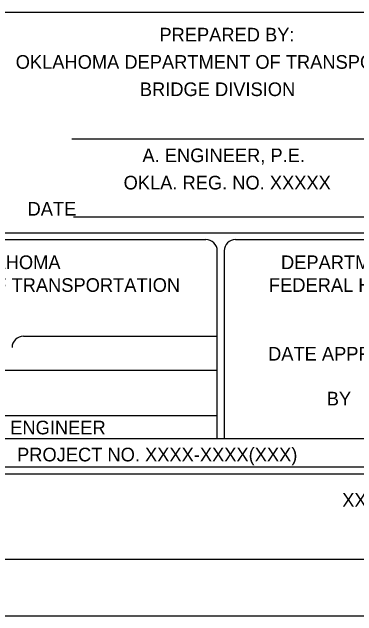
# Model space of a CAD drawing. Extents: x 1458004.1 to 1458040.9, y 194172.7 to 194198.1.
# Drawn here: x 1458033.92 to 1458036.94, y 194172.74 to 194178.05 of the extents above; entities that cross this region are included whole.
import ezdxf

# ---------------------------------------------------------------- set-up
doc = ezdxf.new("R2010")
doc.units = 0
for name, color, linetype in [('Border_0', 7, 'Continuous'), ('Border_9', 7, 'Continuous'), ('IPlot_Plot_Limits', 7, 'Continuous'), ('Text_0', 7, 'Continuous'), ('Text_Box_3', 7, 'Continuous'), ('Text_Box_4', 7, 'Continuous')]:
    doc.layers.add(name, color=color, linetype=linetype)

msp = doc.modelspace()

# ---------------------------------------------------------------- linework, layer by layer
at = {"layer": 'Border_0'}
msp.add_line((1458005.56, 194173.2392), (1458040.06, 194173.2392), dxfattribs=at)
at = {"layer": 'Border_9'}
msp.add_line((1458007.31, 194173.9892), (1458039.31, 194173.9892), dxfattribs=at)
at = {"layer": 'IPlot_Plot_Limits'}
msp.add_line((1458004.06, 194172.7392), (1458040.06, 194172.7392), dxfattribs=at)
at = {"layer": 'Text_Box_3'}
for p, q in [((1458034.4546, 194176.2458), (1458037.3838, 194176.2458)), ((1458034.0167, 194175.1975), (1458035.7183, 194175.1975)), ((1458035.7183, 194174.8975), (1458033.3167, 194174.8975)), ((1458035.7183, 194174.4983), (1458033.2167, 194174.4983))]:
    msp.add_line(p, q, dxfattribs=at)
msp.add_arc((1458034.0168, 194175.0983), 0.1, 90, 180, dxfattribs=at)
at = {"layer": 'Text_Box_4'}
for p, q in [((1458032.0967, 194178.0467), (1458039.4, 194178.0467)), ((1458034.4426, 194176.9319), (1458037.3717, 194176.9319)), ((1458032.0967, 194176.1075), (1458039.4, 194176.1075)), ((1458032.0967, 194176.0475), (1458035.6183, 194176.0475)), ((1458035.8783, 194176.0475), (1458039.4, 194176.0475)), ((1458035.7183, 194174.2983), (1458035.7183, 194175.9475)), ((1458035.7783, 194175.9475), (1458035.7783, 194174.2983)), ((1458031.9967, 194174.2983), (1458039.5, 194174.2983)), ((1458031.9967, 194174.0483), (1458039.3092, 194174.0483))]:
    msp.add_line(p, q, dxfattribs=at)
for centre, start, end in [((1458035.6181, 194175.948), 0, 90), ((1458035.8781, 194175.948), 90, 180)]:
    msp.add_arc(centre, 0.1, start, end, dxfattribs=at)

# ---------------------------------------------------------------- texts
at = {"layer": 'Text_0'}
for s, p in [('PREPARED BY:', (1458035.21, 194177.7883)), ('OKLAHOMA DEPARTMENT OF TRANSPORTATION', (1458033.9483, 194177.5483)), ('BRIDGE DIVISION', (1458035.0383, 194177.3083)), ('A. ENGINEER, P.E.', (1458035.0611, 194176.7275)), ('OKLA. REG. NO. XXXXX', (1458034.8957, 194176.4875)), ('DATE', (1458034.0525, 194176.2575)), ('OKLAHOMA ', (1458033.4325, 194175.7875)), ('DEPARTMENT OF TRANSPORTATION', (1458036.2775, 194175.7875)), ('DEPARTMENT OF TRANSPORTATION', (1458032.4942, 194175.5875)), ('FEDERAL HIGHWAY ADMINISTRATION', (1458036.1717, 194175.5875)), ('DATE APPROVED', (1458036.1642, 194174.9833)), ('BY', (1458036.6792, 194174.5892)), ('CHIEF ENGINEER', (1458033.3742, 194174.335)), ('PROJECT NO. XXXX-XXXX(XXX)', (1458033.9605, 194174.0975)), ('XXXX COUNTY    SH-XXX', (1458036.8153, 194173.6983))]:
    msp.add_text(s, height=0.12, dxfattribs=at).set_placement(p)

doc.saveas('drawing.dxf')
